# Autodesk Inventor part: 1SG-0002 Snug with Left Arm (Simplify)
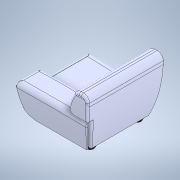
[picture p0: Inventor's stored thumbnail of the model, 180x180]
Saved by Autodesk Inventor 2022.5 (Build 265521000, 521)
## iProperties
Created: 2025-08
Part Number: 1SG-0002 Snug with Left Arm (Simplify)
Material: Generic
Document SubType Name: Modeling
Designer: Mark.Glazzard
Density: 1 g/cm^3
Appearance: Default
Author: Mark.Glazzard
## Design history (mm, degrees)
derived "1SG-0002 Snug with Left Arm (Simplify).iam"
body "Solid1"
body "Solid2"
body "Solid3"
body "Solid4"
body "Solid5"
body "Solid6"
body "Solid7"
